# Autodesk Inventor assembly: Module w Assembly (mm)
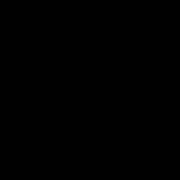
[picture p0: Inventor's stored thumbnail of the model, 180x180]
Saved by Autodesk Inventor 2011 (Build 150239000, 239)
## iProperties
Created: 2006-10
Part Number: Module w Assembly (mm)
Document SubType Name: Assembly
Designer: Wally Jones
Author: Wally Jones
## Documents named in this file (1)
- C:\CAD Courses 1\Inventor\Templates\Metric\Modules Assembly (mm).iam
